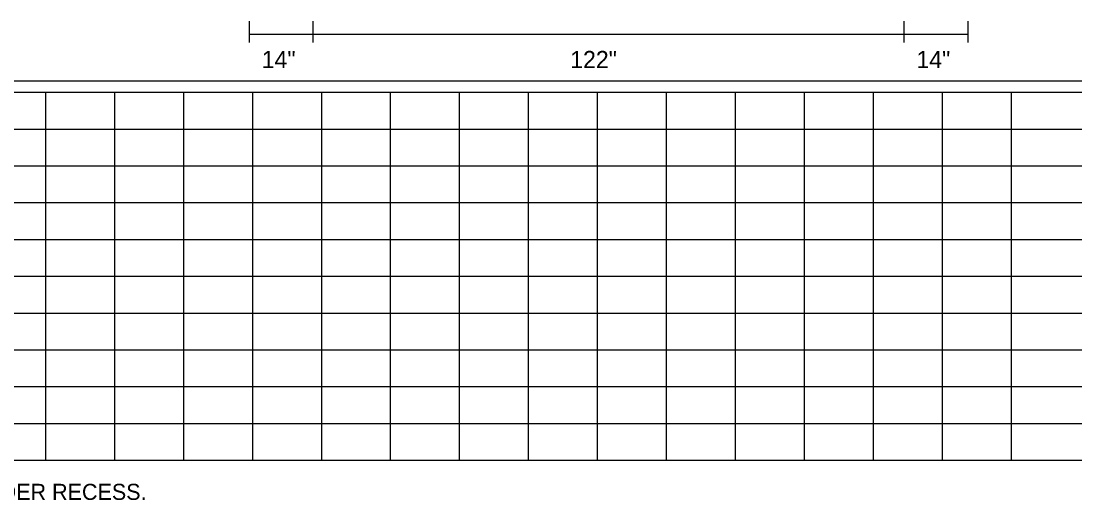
# Model space of a CAD drawing. Extents: x 10268312 to 10268471, y 2141099 to 2141204.
# Drawn here: x 10268380.92 to 10268426.76, y 2141110.37 to 2141131.32 of the extents above; entities that cross this region are included whole.
import ezdxf

# ---------------------------------------------------------------- set-up
doc = ezdxf.new("R2010")
doc.units = 0
for name, color, linetype in [('GSDims', 7, 'Continuous'), ('SumBoxLines_dp', 7, 'Continuous'), ('SumBoxLinesMin_dp', 7, 'Continuous'), ('TextLabel', 7, 'Continuous')]:
    doc.layers.add(name, color=color, linetype=linetype)

msp = doc.modelspace()

# ---------------------------------------------------------------- linework, layer by layer
at = {"layer": 'GSDims'}
for p, q in [((10268390.842, 2141131.322), (10268390.842, 2141130.384)), ((10268393.615, 2141131.322), (10268393.615, 2141130.384)), ((10268393.615, 2141131.322), (10268393.615, 2141130.384)), ((10268419.319, 2141131.322), (10268419.319, 2141130.384)), ((10268419.319, 2141131.322), (10268419.319, 2141130.384)), ((10268422.092, 2141131.322), (10268422.092, 2141130.384)), ((10268390.842, 2141130.759), (10268393.615, 2141130.759)), ((10268393.615, 2141130.759), (10268419.319, 2141130.759)), ((10268419.319, 2141130.759), (10268422.092, 2141130.759))]:
    msp.add_line(p, q, dxfattribs=at)
at = {"layer": 'SumBoxLines_dp'}
for p, q in [((10268341.73, 2141128.728), (10268470.98, 2141128.728)), ((10268318.48, 2141128.228), (10268470.98, 2141128.228)), ((10268381.98, 2141128.228), (10268381.98, 2141121.828)), ((10268384.98, 2141128.228), (10268384.98, 2141121.828)), ((10268387.98, 2141128.228), (10268387.98, 2141121.828)), ((10268390.98, 2141128.228), (10268390.98, 2141121.828)), ((10268393.98, 2141128.228), (10268393.98, 2141121.828)), ((10268396.98, 2141128.228), (10268396.98, 2141121.828)), ((10268399.98, 2141128.228), (10268399.98, 2141121.828)), ((10268402.98, 2141128.228), (10268402.98, 2141121.828)), ((10268405.98, 2141128.228), (10268405.98, 2141121.828)), ((10268408.98, 2141128.228), (10268408.98, 2141112.228)), ((10268411.98, 2141128.228), (10268411.98, 2141112.228)), ((10268414.98, 2141128.228), (10268414.98, 2141112.228)), ((10268417.98, 2141128.228), (10268417.98, 2141112.228)), ((10268420.98, 2141128.228), (10268420.98, 2141112.228)), ((10268423.98, 2141128.228), (10268423.98, 2141112.228)), ((10268318.48, 2141125.028), (10268470.98, 2141125.028)), ((10268318.48, 2141121.828), (10268470.98, 2141121.828)), ((10268381.98, 2141121.828), (10268381.98, 2141112.228)), ((10268384.98, 2141121.828), (10268384.98, 2141112.228)), ((10268387.98, 2141121.828), (10268387.98, 2141112.228)), ((10268390.98, 2141121.828), (10268390.98, 2141112.228)), ((10268393.98, 2141121.828), (10268393.98, 2141112.228)), ((10268396.98, 2141121.828), (10268396.98, 2141112.228)), ((10268399.98, 2141121.828), (10268399.98, 2141112.228)), ((10268402.98, 2141121.828), (10268402.98, 2141112.228)), ((10268405.98, 2141121.828), (10268405.98, 2141112.228)), ((10268318.48, 2141118.628), (10268470.98, 2141118.628)), ((10268318.48, 2141115.428), (10268470.98, 2141115.428)), ((10268318.48, 2141112.228), (10268470.98, 2141112.228))]:
    msp.add_line(p, q, dxfattribs=at)
at = {"layer": 'SumBoxLinesMin_dp'}
for p, q in [((10268318.48, 2141126.628), (10268470.98, 2141126.628)), ((10268318.48, 2141123.428), (10268470.98, 2141123.428)), ((10268318.48, 2141120.228), (10268470.98, 2141120.228)), ((10268318.48, 2141117.028), (10268470.98, 2141117.028)), ((10268318.48, 2141113.828), (10268470.98, 2141113.828))]:
    msp.add_line(p, q, dxfattribs=at)

# ---------------------------------------------------------------- texts
at = {"layer": 'GSDims'}
for s, p in [('14"', (10268391.387, 2141129.275)), ('122"', (10268404.805, 2141129.275)), ('14"', (10268419.864, 2141129.275))]:
    msp.add_text(s, height=0.75, dxfattribs=at).set_placement(p)
at = {"layer": 'TextLabel'}
msp.add_text('NOTE:  WIDTH - HORIZONTAL SPACING DIMENSIONS ARE IN INCHES.  END DIMENSIONS INCLUDE BORDER WIDTH, MARGIN AND BORDER RECESS.', height=0.700021, dxfattribs=at).set_placement((10268319.18, 2141110.504))

doc.saveas('drawing.dxf')
